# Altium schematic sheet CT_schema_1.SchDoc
size 502 x 463 mm
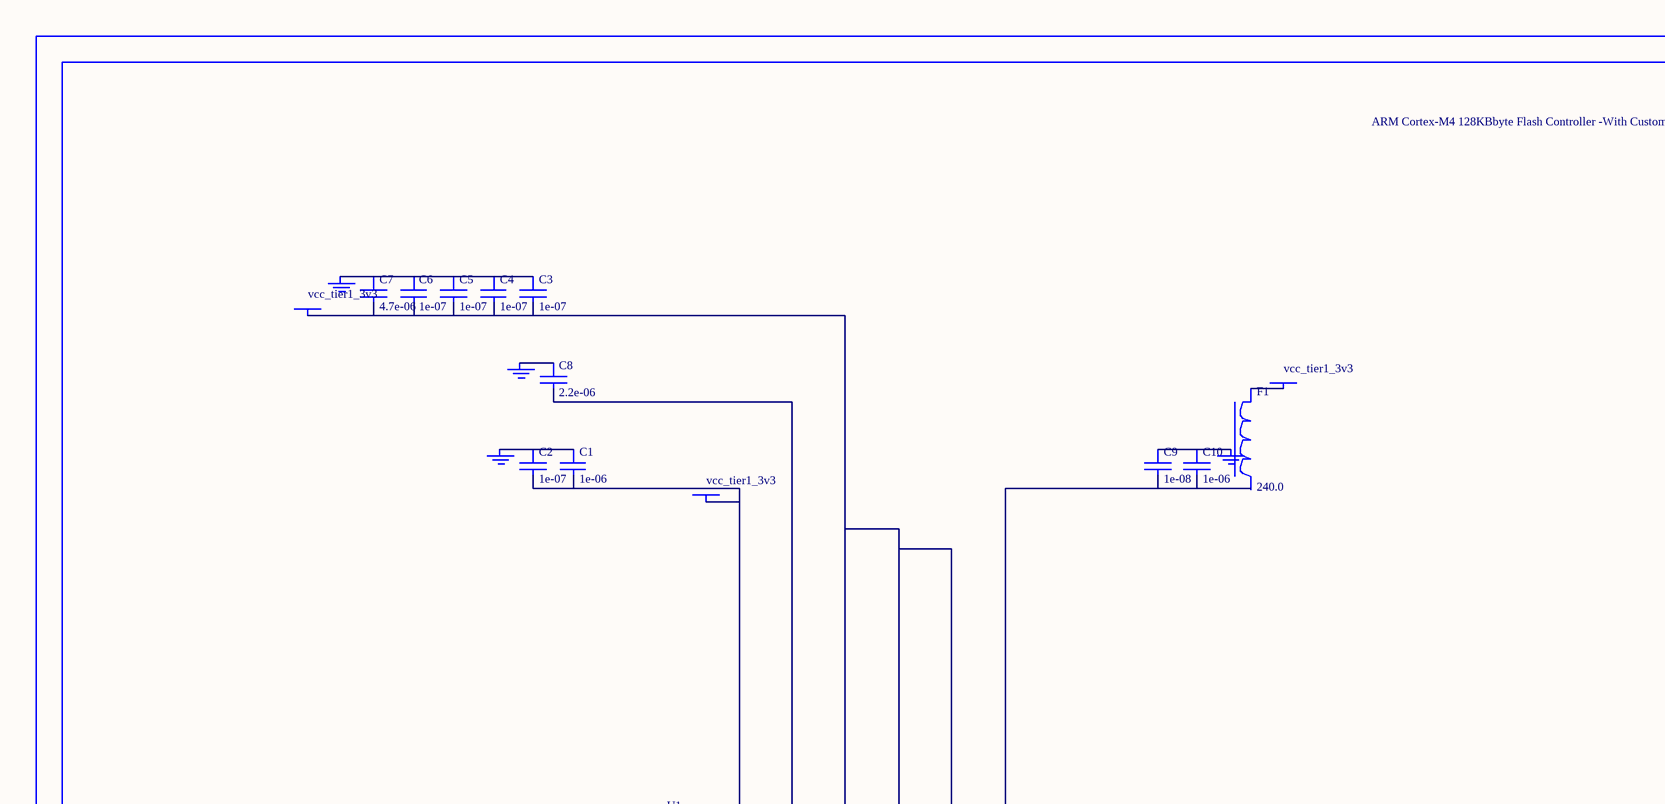
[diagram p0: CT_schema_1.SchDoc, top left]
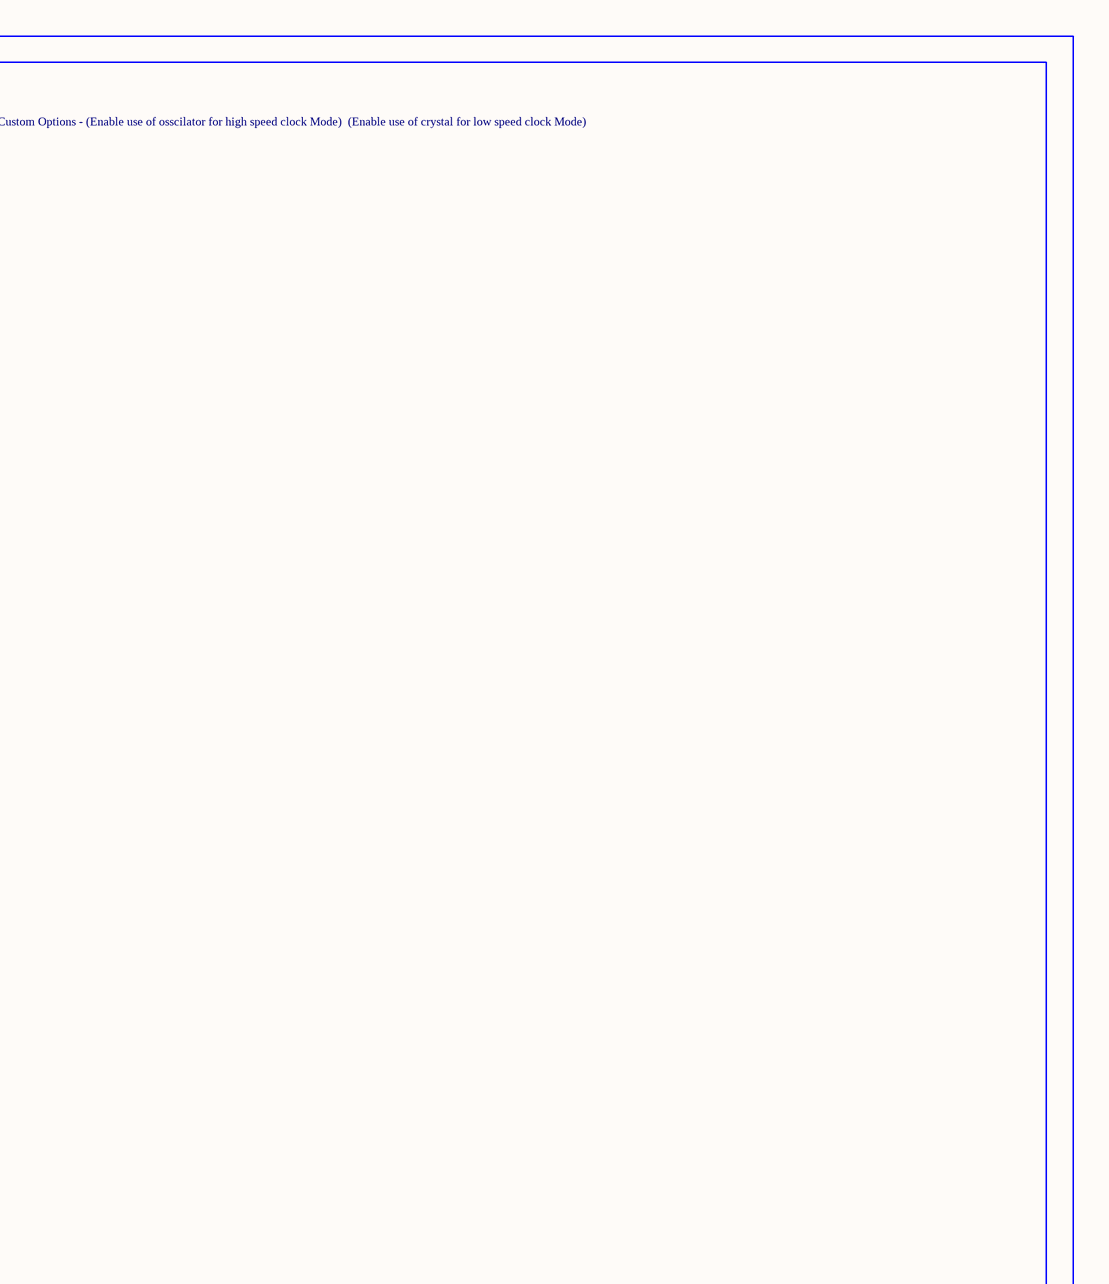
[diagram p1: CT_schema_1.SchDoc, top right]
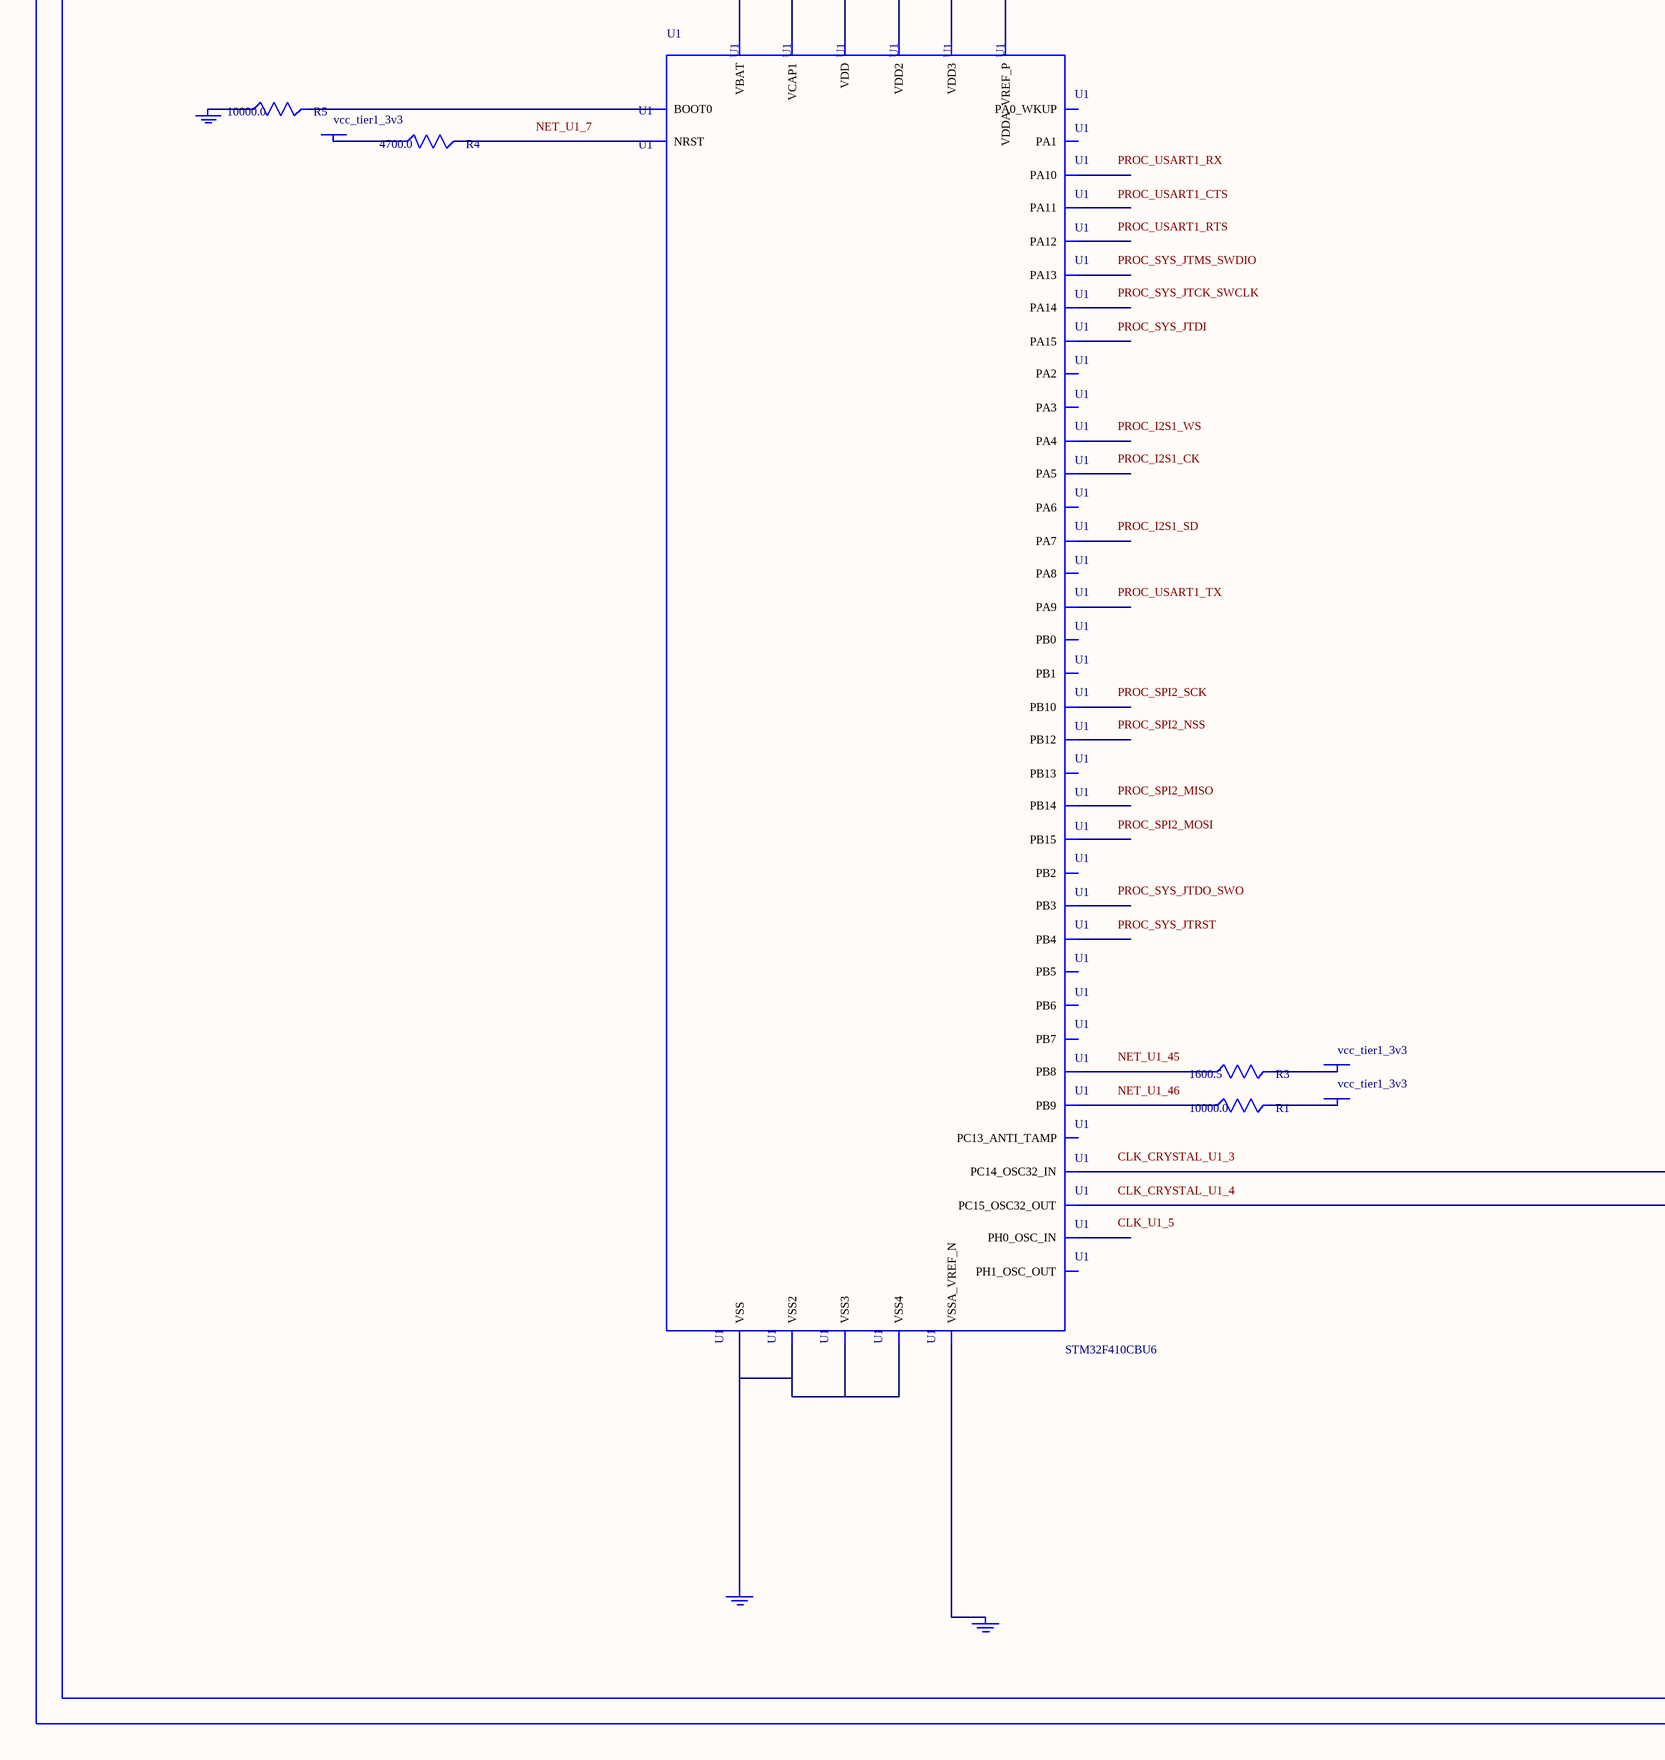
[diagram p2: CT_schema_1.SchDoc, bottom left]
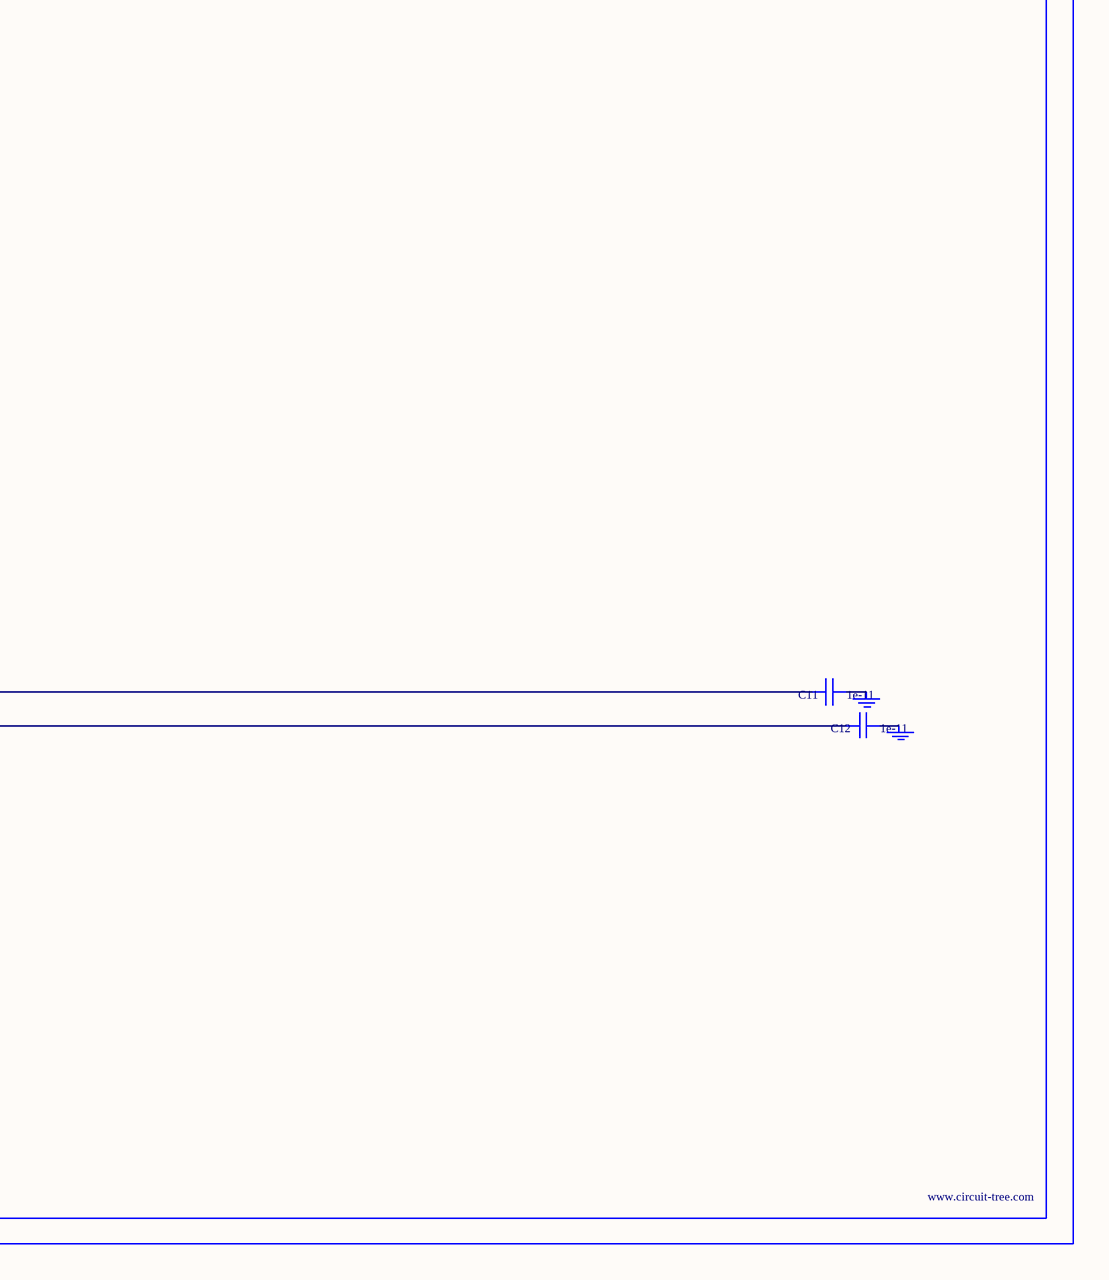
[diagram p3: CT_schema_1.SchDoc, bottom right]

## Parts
BORDER0  (no value)
C1  1e-06  [C0603]
C2  1e-07  [C0603]
C3  1e-07  [C0603]
C4  1e-07  [C0603]
C5  1e-07  [C0603]
C6  1e-07  [C0603]
C7  4.7e-06  [C0603]
C8  2.2e-06  [C0603]
C9  1e-08  [C0603]
C10  1e-06  [C0603]
C11  1e-11  [C0402]
C12  1e-11  [C0402]
F1  240.0  [L0603]
GND_INSTANCE_0_0  (no value)
GND_INSTANCE_0_1  (no value)
GND_INSTANCE_0_2  (no value)
GND_INSTANCE_0_3  (no value)
GND_INSTANCE_0_4  (no value)
GND_INSTANCE_0_5  (no value)
GND_INSTANCE_0_6  (no value)
GND_INSTANCE_0_7  (no value)
GND_INSTANCE_0_8  (no value)
POWER_INSTANCE_0_0  vcc_tier1_3v3
POWER_INSTANCE_0_1  vcc_tier1_3v3
POWER_INSTANCE_0_2  vcc_tier1_3v3
POWER_INSTANCE_0_3  vcc_tier1_3v3
POWER_INSTANCE_0_4  vcc_tier1_3v3
POWER_INSTANCE_0_5  vcc_tier1_3v3
R1  10000.0  [R0603]
R3  1600.5  [R0603]
R4  4700.0  [R0603]
R5  10000.0  [R0603]
U1  STM32F410CBU6  [UFQFPN48]

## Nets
NetC1_1: C1.1 C2.1 GND_INSTANCE_0_0.0(GND)
NetC1_2: C1.2 C2.2 POWER_INSTANCE_0_0.0(PWR) U1.1(VBAT)
NetC3_1: C3.1 C4.1 C5.1 C6.1 C7.1 GND_INSTANCE_0_6.0(GND)
NetC3_2: C3.2 C4.2 C5.2 C6.2 C7.2 POWER_INSTANCE_0_2.0(PWR) U1.24(VDD) U1.36(VDD2) U1.48(VDD3)
NetC8_1: C8.1 GND_INSTANCE_0_5.0(GND)
NetC8_2: C8.2 U1.22(VCAP1)
NetC9_1: C9.1 C10.1 GND_INSTANCE_0_4.0(GND)
NetC9_2: C9.2 C10.2 U1.9(VDDA_VREF_P)
NetC11_1: C11.1 GND_INSTANCE_0_1.0(GND)
NetC11_2: C11.2 U1.3(PC14_OSC32_IN)
NetC12_1: C12.1 GND_INSTANCE_0_2.0(GND)
NetC12_2: C12.2 U1.4(PC15_OSC32_OUT)
NetF1_1: F1.1 POWER_INSTANCE_0_1.0(PWR)
NetGND_INSTANCE_0_3_0: GND_INSTANCE_0_3.0(GND) U1.8(VSSA_VREF_N)
NetGND_INSTANCE_0_7_0: GND_INSTANCE_0_7.0(GND) R5.1
NetGND_INSTANCE_0_8_0: GND_INSTANCE_0_8.0(GND) U1.23(VSS) U1.35(VSS2) U1.47(VSS3) U1.49(VSS4)
NetPOWER_INSTANCE_0_3_0: POWER_INSTANCE_0_3.0(PWR) R4.1
NetPOWER_INSTANCE_0_4_0: POWER_INSTANCE_0_4.0(PWR) R3.2
NetPOWER_INSTANCE_0_5_0: POWER_INSTANCE_0_5.0(PWR) R1.2
NetR1_1: R1.1 U1.46(PB9)
NetR3_1: R3.1 U1.45(PB8)
NetR4_2: R4.2 U1.7(NRST)
NetR5_2: R5.2 U1.44(BOOT0)

Not connected (* = marked no-connect by the designer): F1 2; U1 2(PC13_ANTI_TAMP) 5(PH0_OSC_IN) 6(PH1_OSC_OUT) 10(PA0_WKUP) 11(PA1) 12(PA2) 13(PA3) 14(PA4) 15(PA5) 16(PA6) 17(PA7) 18(PB0) 19(PB1) 20(PB2) 21(PB10) 25(PB12) 26(PB13) 27(PB14) 28(PB15) 29(PA8) 30(PA9) 31(PA10) 32(PA11) 33(PA12) 34(PA13) 37(PA14) 38(PA15) 39(PB3) 40(PB4) 41(PB5) 42(PB6) 43(PB7)

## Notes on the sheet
- Labels drawn without touching a wire or pin: CLK_CRYSTAL_U1_3, CLK_CRYSTAL_U1_4, CLK_U1_5, NET_U1_7, NET_U1_45, NET_U1_46, PROC_I2S1_CK, PROC_I2S1_SD, PROC_I2S1_WS, PROC_SPI2_MISO, PROC_SPI2_MOSI, PROC_SPI2_NSS, PROC_SPI2_SCK, PROC_SYS_JTCK_SWCLK, PROC_SYS_JTDI, PROC_SYS_JTDO_SWO, PROC_SYS_JTMS_SWDIO, PROC_SYS_JTRST, PROC_USART1_CTS, PROC_USART1_RTS, PROC_USART1_RX, PROC_USART1_TX

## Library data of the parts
BORDER0 = BORDER_PAGE0
C1 C10 = C0603C105K3RACTU
C2-C6 = 06035C104K4Z2A
C7 = GRM188R6YA475KE15D
C8 = C0603C225K8RACTU
C9 = 06035C103K4Z2A
C11 C12 = C0402C100K3GACTU
F1 = Z0603C241ASMST
GND_INSTANCE_0_0-GND_INSTANCE_0_8 = GND
POWER_INSTANCE_0_0-POWER_INSTANCE_0_5 = PWR
R1 R5 = RC0603JR-0710KL
R3 = R3
R4 = RC0603JR-074K7L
